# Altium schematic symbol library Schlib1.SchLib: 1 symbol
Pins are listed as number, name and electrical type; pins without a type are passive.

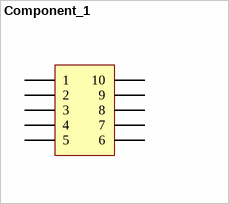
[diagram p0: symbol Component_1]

## Component_1
designator U?, comment Used in BOM report
SymbolVersion: use current date i.e. 2008-05-20; SymbolCreator: Use a-id; CompType: Used in some BOM reports.  Useful for finding later.; U/M: EA, IN, or GM
footprint PCBComponent_1
pins: 1, 2, 3, 4, 5, 6, 7, 8, 9, 10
